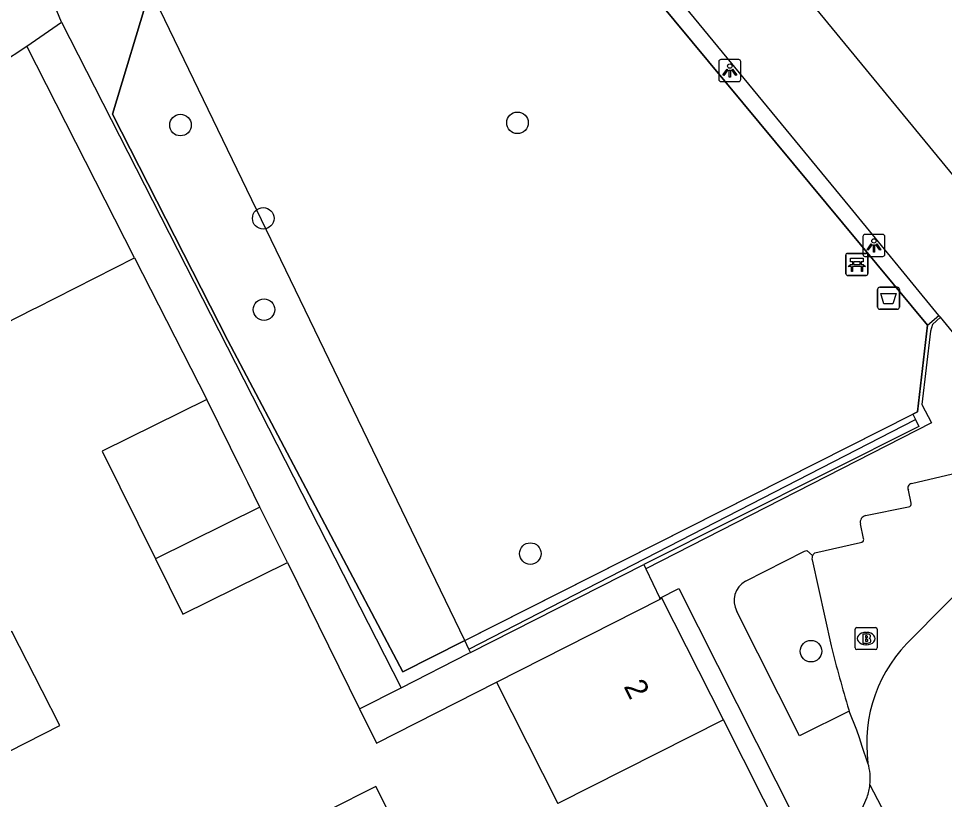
# Model space of a CAD drawing. Extents: x 162347 to 162868, y 381221 to 381813.
# Drawn here: x 162386.78 to 162428.75, y 381653.9 to 381689.32 of the extents above; entities that cross this region are included whole.
import ezdxf

# ---------------------------------------------------------------- set-up
doc = ezdxf.new("R2010")
doc.units = 0
for name, color, linetype in [('IMGEO_Afvalbak', 7, 'Continuous'), ('IMGEO_Bank', 7, 'Continuous'), ('IMGEO_Boom', 7, 'Continuous'), ('IMGEO_Brandkraan', 7, 'Continuous'), ('IMGEO_Groenvoorziening', 7, 'Continuous'), ('IMGEO_Haag', 7, 'Continuous'), ('IMGEO_Hek', 7, 'Continuous'), ('IMGEO_Lichtpunt', 7, 'Continuous'), ('IMGEO_Pand', 7, 'Continuous'), ('IMGEO_Pand_nummerreeks', 7, 'Continuous'), ('IMGEO_Parkeervlak_open', 7, 'Continuous'), ('IMGEO_Rijbaan_lokaal_open', 7, 'Continuous'), ('IMGEO_Voetpad_open', 7, 'Continuous')]:
    doc.layers.add(name, color=color, linetype=linetype)

msp = doc.modelspace()

# ---------------------------------------------------------------- linework, layer by layer
at = {"layer": 'IMGEO_Afvalbak'}
for p, q in [((162425.716, 381676.229), (162425.716, 381677.029)), ((162425.716, 381677.029), (162425.716, 381676.229)), ((162425.816, 381677.129), (162426.606, 381677.129)), ((162426.606, 381677.129), (162425.816, 381677.129)), ((162426.706, 381677.029), (162426.706, 381676.229)), ((162426.706, 381676.229), (162426.706, 381677.029)), ((162426.606, 381676.129), (162425.816, 381676.129)), ((162425.816, 381676.129), (162426.606, 381676.129))]:
    msp.add_line(p, q, dxfattribs=at)
msp.add_lwpolyline([(162425.859, 381676.843), (162426.563, 381676.843), (162426.414, 381676.373), (162426.008, 381676.373), (162425.859, 381676.843)], dxfattribs=at)
for centre, start, end in [((162425.816, 381677.029), 90, 180), ((162425.816, 381677.029), 90, 180), ((162426.606, 381677.029), 0, 90), ((162426.606, 381677.029), 360, 90), ((162425.816, 381676.229), 180, 270), ((162425.816, 381676.229), 180, 270), ((162426.606, 381676.229), 270, 0), ((162426.606, 381676.229), 270, 0)]:
    msp.add_arc(centre, 0.1, start, end, dxfattribs=at)
at = {"layer": 'IMGEO_Bank'}
for p, q in [((162424.357, 381678.665), (162425.198, 381678.665)), ((162425.198, 381678.665), (162424.357, 381678.665)), ((162424.282, 381677.74), (162424.282, 381678.581)), ((162424.282, 381678.581), (162424.282, 381677.74)), ((162424.591, 381678.171), (162424.591, 381678.277)), ((162424.635, 381678.277), (162424.635, 381678.171)), ((162424.923, 381678.283), (162424.641, 381678.283)), ((162424.929, 381678.171), (162424.929, 381678.277)), ((162424.973, 381678.277), (162424.973, 381678.171)), ((162425.282, 381678.59), (162425.282, 381677.749)), ((162425.282, 381677.749), (162425.282, 381678.59)), ((162424.979, 381678.063), (162424.586, 381678.063)), ((162424.641, 381678.165), (162424.923, 381678.165)), ((162425.207, 381677.665), (162424.366, 381677.665)), ((162424.366, 381677.665), (162425.207, 381677.665))]:
    msp.add_line(p, q, dxfattribs=at)
for points in [[(162424.585, 381678.283), (162424.499, 381678.283), (162424.499, 381678.444), (162425.062, 381678.444), (162425.062, 381678.283), (162424.979, 381678.283)], [(162424.529, 381678.063), (162424.387, 381678.063), (162424.499, 381678.165), (162424.585, 381678.165)], [(162424.579, 381678.056), (162424.579, 381677.849), (162424.536, 381677.849), (162424.536, 381678.056)], [(162424.979, 381678.165), (162425.062, 381678.165), (162425.174, 381678.063), (162425.035, 381678.063)], [(162425.029, 381678.056), (162425.029, 381677.849), (162424.985, 381677.849), (162424.985, 381678.056)]]:
    msp.add_lwpolyline(points, dxfattribs=at)
for centre, radius, start, end in [((162424.36, 381678.587), 0.0779, 92.4484, 184.2845), ((162424.36, 381678.587), 0.0779, 92.4484, 184.2845), ((162425.204, 381678.587), 0.0779, 2.4484, 94.2845), ((162425.204, 381678.587), 0.0779, 2.4484, 94.2845), ((162424.584, 381678.276), 0.00671, 2.8957, 87.1043), ((162424.641, 381678.276), 0.00671, 92.8957, 177.1043), ((162424.923, 381678.276), 0.00671, 2.8957, 87.1043), ((162424.98, 381678.276), 0.00671, 92.8957, 177.1043), ((162424.529, 381678.056), 0.00671, 2.8957, 87.1043), ((162424.586, 381678.056), 0.00671, 92.8957, 177.1043), ((162424.584, 381678.172), 0.00671, 272.8957, 357.1043), ((162424.641, 381678.172), 0.00671, 182.8957, 267.1043), ((162424.923, 381678.172), 0.00671, 272.8957, 357.1043), ((162424.98, 381678.172), 0.00671, 182.8957, 267.1043), ((162424.978, 381678.056), 0.00671, 2.8957, 87.1043), ((162425.035, 381678.056), 0.00671, 92.8957, 177.1043), ((162424.36, 381677.743), 0.0779, 182.4484, 274.2845), ((162424.36, 381677.743), 0.0779, 182.4484, 274.2845), ((162425.204, 381677.743), 0.0779, 272.4484, 4.2845), ((162425.204, 381677.743), 0.0779, 272.4484, 4.2845)]:
    msp.add_arc(centre, radius, start, end, dxfattribs=at)
at = {"layer": 'IMGEO_Boom'}
for centre in [(162394.119, 381684.483), (162409.395, 381684.587), (162397.872, 381680.254), (162397.906, 381676.115), (162409.979, 381665.051), (162422.7, 381660.625)]:
    msp.add_circle(centre, 0.489, dxfattribs=at)
at = {"layer": 'IMGEO_Brandkraan'}
for p, q in [((162424.701, 381660.77), (162424.701, 381661.622)), ((162424.776, 381661.696), (162425.628, 381661.696)), ((162425.189, 381661.476), (162425.214, 381661.476)), ((162425.702, 381661.622), (162425.702, 381660.77)), ((162425.628, 381660.696), (162424.776, 381660.696)), ((162425.212, 381660.916), (162425.187, 381660.916))]:
    msp.add_line(p, q, dxfattribs=at)
for points in [[(162424.701, 381660.77), (162424.701, 381661.622)], [(162424.776, 381661.696), (162425.628, 381661.696)], [(162425.702, 381661.622), (162425.702, 381660.77)], [(162425.049, 381661.396), (162425.049, 381660.996), (162425.262, 381660.996)], [(162425.28, 381661.396), (162425.049, 381661.396)], [(162425.228, 381661.315), (162425.174, 381661.315), (162425.174, 381661.239)], [(162425.174, 381661.239), (162425.227, 381661.239)], [(162425.236, 381661.163), (162425.174, 381661.163), (162425.174, 381661.082)], [(162425.174, 381661.082), (162425.236, 381661.082)], [(162425.628, 381660.696), (162424.776, 381660.696)]]:
    msp.add_lwpolyline(points, dxfattribs=at)
for centre, radius, start, end in [((162424.778, 381661.62), 0.0765, 91.552, 178.448), ((162424.778, 381661.62), 0.0765, 91.552, 178.448), ((162425.626, 381661.62), 0.0765, 1.552, 88.448), ((162425.626, 381661.62), 0.0765, 1.552, 88.448), ((162425.229, 381661.277), 0.0379, 267.8285, 90.9355), ((162425.237, 381661.122), 0.0404, 269.8759, 90.5077), ((162425.284, 381661.251), 0.145, 59.4692, 91.5367), ((162425.309, 381661.298), 0.0922, 285.5137, 58.1501), ((162425.314, 381661.106), 0.105, 301.3115, 78.989), ((162424.778, 381660.772), 0.0765, 181.552, 268.448), ((162424.778, 381660.772), 0.0765, 181.552, 268.448), ((162425.268, 381661.247), 0.251, 268.6676, 293.5347), ((162425.626, 381660.772), 0.0765, 271.552, 358.448), ((162425.626, 381660.772), 0.0765, 271.552, 358.448)]:
    msp.add_arc(centre, radius, start, end, dxfattribs=at)
for centre, major_axis, ratio, start_param, end_param in [((162425.188, 381661.196), (-0.387, 0.002), 0.722429, 4.712389, 7.853982), ((162425.213, 381661.196), (-0.39, 0.002), 0.717154, 1.570796, 4.712389)]:
    msp.add_ellipse(centre, major_axis=major_axis, ratio=ratio, start_param=start_param, end_param=end_param, dxfattribs=at)
at = {"layer": 'IMGEO_Groenvoorziening'}
for points in [[(162407.006, 381661.112), (162406.916, 381661.066), (162404.205, 381659.696), (162396.273, 381674.72), (162391.044, 381684.973), (162392.753, 381690.648)], [(162407.006, 381661.112), (162392.753, 381690.648)], [(162427.975, 381675.41), (162427.522, 381671.476), (162427.316, 381671.372)]]:
    msp.add_lwpolyline(points, dxfattribs=at)
at = {"layer": 'IMGEO_Haag'}
for points in [[(162405.833, 381702.099), (162427.975, 381675.41)], [(162427.975, 381675.41), (162428.502, 381675.847)], [(162407.006, 381661.112), (162427.316, 381671.372)], [(162407.195, 381660.721), (162427.438, 381671.131)], [(162427.438, 381671.131), (162427.596, 381670.818), (162415.118, 381664.562)], [(162427.316, 381671.372), (162427.438, 381671.131)], [(162407.195, 381660.721), (162407.006, 381661.112)], [(162407.267, 381660.571), (162407.195, 381660.721)]]:
    msp.add_lwpolyline(points, dxfattribs=at)
at = {"layer": 'IMGEO_Hek'}
for points in [[(162427.975, 381675.41), (162405.833, 381702.099)], [(162392.753, 381690.648), (162391.044, 381684.973), (162396.273, 381674.72), (162404.205, 381659.696), (162406.916, 381661.066)], [(162427.316, 381671.372), (162427.522, 381671.476), (162427.975, 381675.41)], [(162406.916, 381661.066), (162427.316, 381671.372)]]:
    msp.add_lwpolyline(points, dxfattribs=at)
at = {"layer": 'IMGEO_Lichtpunt'}
for p, q in [((162418.522, 381687.359), (162418.522, 381686.552)), ((162418.522, 381687.359), (162418.522, 381686.552)), ((162419.424, 381687.454), (162418.616, 381687.454)), ((162419.424, 381687.454), (162418.616, 381687.454)), ((162419.518, 381686.552), (162419.518, 381687.359)), ((162419.518, 381686.552), (162419.518, 381687.359)), ((162418.616, 381686.458), (162419.424, 381686.458)), ((162418.616, 381686.458), (162419.424, 381686.458)), ((162425.956, 381679.525), (162425.148, 381679.525)), ((162425.956, 381679.525), (162425.148, 381679.525)), ((162425.054, 381679.43), (162425.054, 381678.623)), ((162425.054, 381679.43), (162425.054, 381678.623)), ((162426.05, 381678.623), (162426.05, 381679.43)), ((162426.05, 381678.623), (162426.05, 381679.43)), ((162425.148, 381678.529), (162425.956, 381678.529)), ((162425.148, 381678.529), (162425.956, 381678.529))]:
    msp.add_line(p, q, dxfattribs=at)
for points in [[(162418.896, 381687.023), (162418.935, 381686.995), (162418.747, 381686.733), (162418.709, 381686.76), (162418.896, 381687.023)], [(162418.998, 381686.975), (162419.045, 381686.975), (162419.045, 381686.653), (162418.998, 381686.653), (162418.998, 381686.975)], [(162419.108, 381686.995), (162419.146, 381687.022), (162419.333, 381686.76), (162419.294, 381686.732), (162419.108, 381686.995)], [(162425.428, 381679.094), (162425.467, 381679.066), (162425.279, 381678.804), (162425.241, 381678.831), (162425.428, 381679.094)], [(162425.64, 381679.066), (162425.678, 381679.093), (162425.865, 381678.831), (162425.826, 381678.803), (162425.64, 381679.066)], [(162425.53, 381679.046), (162425.577, 381679.046), (162425.577, 381678.724), (162425.53, 381678.724), (162425.53, 381679.046)]]:
    msp.add_lwpolyline(points, dxfattribs=at)
for centre in [(162419.021, 381687.157), (162425.553, 381679.228)]:
    msp.add_circle(centre, 0.0994, dxfattribs=at)
for centre, start, end in [((162418.616, 381687.359), 90, 180), ((162418.616, 381687.359), 90, 180), ((162419.424, 381687.359), 0, 90), ((162419.424, 381687.359), 0, 90), ((162418.616, 381686.552), 180, 270), ((162418.616, 381686.552), 180, 270), ((162419.424, 381686.552), 270, 0), ((162419.424, 381686.552), 270, 360), ((162425.148, 381679.43), 90, 180), ((162425.148, 381679.43), 90, 180), ((162425.956, 381679.43), 0, 90), ((162425.956, 381679.43), 0, 90), ((162425.148, 381678.623), 180, 270), ((162425.148, 381678.623), 180, 270), ((162425.956, 381678.623), 270, 0), ((162425.956, 381678.623), 270, 360)]:
    msp.add_arc(centre, 0.0946, start, end, dxfattribs=at)
at = {"layer": 'IMGEO_Pand'}
for points in [[(162365.422, 381672.828), (162370.461, 381676.653), (162372.002, 381677.823), (162372.211, 381677.413), (162376.598, 381680.579), (162376.39, 381680.988), (162387.157, 381688.064)], [(162392.04, 381678.467), (162387.157, 381688.064)], [(162380.866, 381672.782), (162387.474, 381676.144), (162387.584, 381676.2), (162392.04, 381678.467)], [(162395.311, 381672.039), (162390.572, 381669.699), (162392.986, 381664.812)], [(162397.724, 381667.152), (162397.166, 381668.282), (162396.929, 381668.763), (162395.311, 381672.039)], [(162397.724, 381667.152), (162392.986, 381664.812)], [(162398.964, 381664.64), (162397.724, 381667.152)], [(162392.986, 381664.812), (162394.227, 381662.3), (162398.964, 381664.64)], [(162408.443, 381659.219), (162415.866, 381662.989)], [(162418.73, 381657.511), (162415.945, 381663.03), (162415.867, 381662.99), (162415.866, 381662.989)], [(162374.408, 381654.239), (162373.886, 381653.972), (162378.488, 381644.927), (162381.742, 381646.582), (162382.855, 381644.417), (162386.146, 381646.123), (162385.019, 381648.298), (162388.244, 381649.97), (162386.203, 381653.979), (162384.898, 381653.315), (162384.079, 381654.925), (162388.651, 381657.252), (162387.852, 381658.821), (162386.481, 381661.514), (162384.132, 381660.319)], [(162408.443, 381659.219), (162411.223, 381653.711)], [(162418.73, 381657.511), (162411.223, 381653.711)], [(162421.45, 381652.12), (162418.73, 381657.511)], [(162404.977, 381650.514), (162402.978, 381654.492), (162400.813, 381653.404)]]:
    msp.add_lwpolyline(points, dxfattribs=at)
at = {"layer": 'IMGEO_Parkeervlak_open'}
for points in [[(162428.502, 381675.847), (162424.466, 381680.783), (162406.648, 381702.432)], [(162428.569, 381675.765), (162428.502, 381675.847)], [(162422.748, 381664.769), (162423.61, 381660.871)], [(162424.41, 381657.97), (162424.433, 381657.912)]]:
    msp.add_lwpolyline(points, dxfattribs=at)
for centre, radius, start, end in [((162423.066, 381664.821), 0.322, 154.5657, 189.2585), ((162502.157, 381680.971), 81.078, 194.35375, 196.48045)]:
    msp.add_arc(centre, radius, start, end, dxfattribs=at)
at = {"layer": 'IMGEO_Rijbaan_lokaal_open'}
for points in [[(162409.377, 381706.246), (162434.507, 381675.673)], [(162433.614, 381667.623), (162427.324, 381661.252)], [(162425.373, 381654.562), (162435.395, 381635.369), (162459.045, 381588.618), (162459.315, 381588.084)]]:
    msp.add_lwpolyline(points, dxfattribs=at)
for centre, radius, start, end in [((162431.809, 381656.43), 6.585, 132.9265, 187.6971), ((162422.893, 381654.833), 2.494, 353.768, 16.6628)]:
    msp.add_arc(centre, radius, start, end, dxfattribs=at)
at = {"layer": 'IMGEO_Voetpad_open'}
for points in [[(162388.726, 381689.153), (162388.407, 381689.921), (162388.277, 381690.743)], [(162387.157, 381688.064), (162388.726, 381689.153)], [(162388.726, 381689.153), (162404.119, 381658.971)], [(162392.04, 381678.467), (162395.311, 381672.039)], [(162428.569, 381675.765), (162428.211, 381675.44), (162428.12, 381675.14), (162427.72, 381671.816), (162428.169, 381670.985), (162415.217, 381664.354)], [(162430.818, 381673.015), (162428.569, 381675.765)], [(162427.256, 381668.227), (162429.375, 381668.726)], [(162427.239, 381667.338), (162427.117, 381667.921)], [(162425.175, 381666.773), (162427.123, 381667.175)], [(162425.083, 381665.728), (162424.938, 381666.401)], [(162422.877, 381665.082), (162424.95, 381665.559)], [(162419.728, 381663.797), (162422.409, 381665.166), (162422.517, 381665.187), (162422.775, 381664.959)], [(162398.964, 381664.64), (162402.236, 381658.014)], [(162407.267, 381660.571), (162415.118, 381664.562)], [(162415.118, 381664.562), (162415.217, 381664.354)], [(162415.217, 381664.354), (162415.849, 381663.025)], [(162415.849, 381663.025), (162416.703, 381663.475), (162450.084, 381597.259), (162455.733, 381586.132)], [(162415.866, 381662.989), (162415.849, 381663.025)], [(162424.433, 381657.912), (162422.177, 381656.792), (162419.338, 381662.432)], [(162404.119, 381658.971), (162407.188, 381660.531), (162407.267, 381660.571)], [(162402.236, 381658.014), (162403.005, 381656.457), (162408.443, 381659.219)], [(162402.236, 381658.014), (162404.119, 381658.971)], [(162425.283, 381655.548), (162425.023, 381656.298), (162424.898, 381656.689), (162424.783, 381657.046), (162424.781, 381657.051), (162424.433, 381657.912)], [(162424.695, 381652.736), (162425.245, 381654.004)]]:
    msp.add_lwpolyline(points, dxfattribs=at)
for centre, radius, start, end in [((162427.29, 381668.027), 0.203, 99.5609, 211.5794), ((162427.126, 381667.295), 0.12, 268.3498, 20.7746), ((162425.248, 381666.465), 0.317, 103.3776, 191.6202), ((162424.96, 381665.688), 0.129, 265.4343, 18.1615), ((162423.06, 381664.826), 0.315, 125.6299, 155.0344), ((162420.221, 381662.918), 1.008, 119.3016, 208.8076), ((162422.895, 381654.837), 2.493, 340.4866, 353.6742)]:
    msp.add_arc(centre, radius, start, end, dxfattribs=at)

# ---------------------------------------------------------------- texts
at = {"layer": 'IMGEO_Pand_nummerreeks'}
msp.add_text('2', height=1, rotation=296.8429, dxfattribs=at).set_placement((162414.194, 381659.031))

doc.saveas('drawing.dxf')
